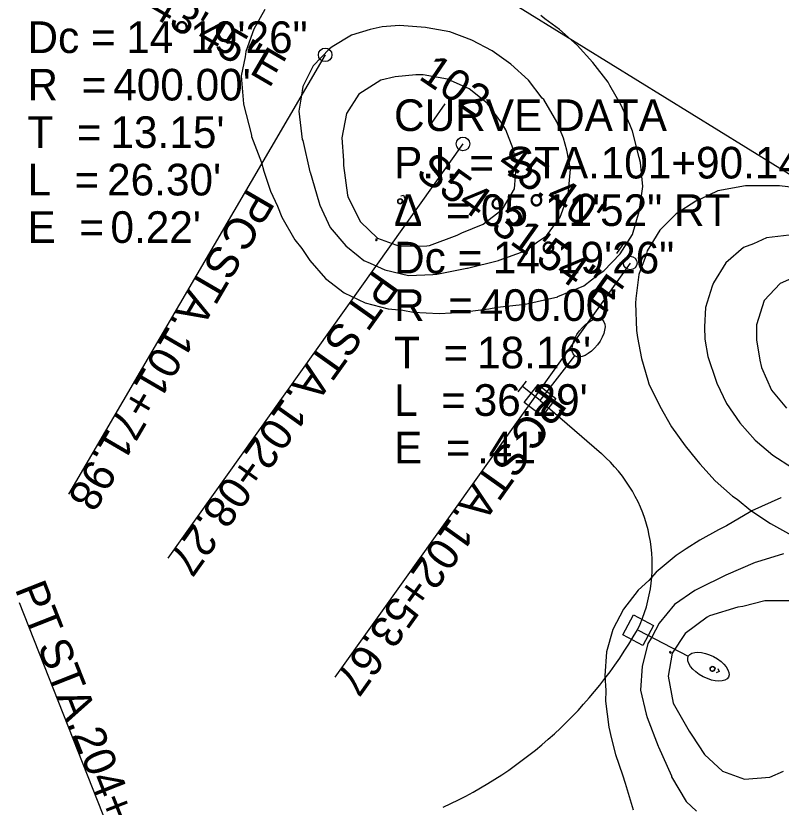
# Model space of a CAD drawing. Extents: x 1598538 to 1602183, y 285823 to 288192.
# Drawn here: x 1600781.1 to 1600950.3, y 286694.3 to 286869.3 of the extents above; entities that cross this region are included whole.
import ezdxf

# ---------------------------------------------------------------- set-up
doc = ezdxf.new("R2010")
doc.units = 0
for name, color, linetype in [('CM_Corridor_Conceptual', 7, 'Continuous'), ('CM_Corridor_Range_Conceptual', 7, 'Continuous'), ('Default', 7, 'Continuous'), ('MD_P_AGB_B', 7, 'Continuous'), ('PV_P_Curb', 7, 'Continuous'), ('PV_P_EOP', 7, 'Continuous'), ('RW_P_Esmt_LA', 7, 'Continuous'), ('RW_P_Esmt_TMP', 7, 'Continuous')]:
    doc.layers.add(name, color=color, linetype=linetype)

msp = doc.modelspace()

# ---------------------------------------------------------------- linework, layer by layer
at = {"layer": 'Default'}
for points in [[(1600836.17, 286870.71), (1600833.67, 286866.3), (1600831.92, 286861.36), (1600831.8, 286860.21), (1600830.92, 286855.99), (1600831.42, 286849.8), (1600831.42, 286849.74), (1600833.17, 286842.9), (1600833.17, 286842.61), (1600835.42, 286836.83), (1600835.92, 286834.96), (1600837.42, 286830.49), (1600838.92, 286827.18), (1600839.92, 286824.74), (1600842.8, 286819.71), (1600844.3, 286817.86), (1600846.05, 286815.18), (1600849.55, 286811.18), (1600853.67, 286808.02), (1600858.3, 286805.83), (1600863.42, 286804.52), (1600866.67, 286804.21), (1600868.92, 286803.74), (1600874.67, 286803.43), (1600877.42, 286803.61), (1600880.92, 286803.86), (1600885.67, 286804.52), (1600887.55, 286804.86), (1600893.67, 286805.55), (1600894.05, 286805.61), (1600900.92, 286807.15), (1600900.92, 286807.18), (1600906.67, 286809.58), (1600910.05, 286812.24), (1600911.05, 286812.9), (1600914.67, 286816.68), (1600917.42, 286820.96), (1600918.92, 286825.99), (1600919.05, 286826.96), (1600919.67, 286831.55), (1600919.17, 286836.83), (1600918.92, 286837.93), (1600917.42, 286843.74), (1600916.8, 286845.24), (1600914.92, 286849.55), (1600912.42, 286853.86), (1600912.05, 286854.58), (1600908.67, 286858.93), (1600905.17, 286862.8), (1600901.3, 286866.27), (1600898.05, 286868.65), (1600897.17, 286869.36)], [(1600956.05, 286830.96), (1600949.92, 286831.65), (1600949.55, 286831.68), (1600942.55, 286831.71), (1600942.42, 286831.71), (1600936.3, 286830.58), (1600932.42, 286828.77), (1600931.42, 286828.33), (1600927.05, 286825.49), (1600923.42, 286821.9), (1600920.67, 286817.33), (1600920.42, 286816.43), (1600918.8, 286812.08), (1600918.17, 286806.8), (1600918.05, 286805.71), (1600918.3, 286799.68), (1600918.55, 286798.11), (1600919.42, 286793.49), (1600920.8, 286788.74), (1600921.05, 286787.93), (1600923.42, 286782.96), (1600926.05, 286778.36), (1600929.05, 286774.15), (1600931.55, 286771.11), (1600932.3, 286770.21), (1600935.67, 286766.43), (1600939.55, 286763.08), (1600940.55, 286762.36), (1600943.55, 286759.9), (1600947.92, 286756.99), (1600952.55, 286754.46)], [(1600865.8, 286828.74), (1600865.55, 286828.55), (1600865.55, 286828.55), (1600865.8, 286828.74), (1600865.8, 286828.74)], [(1600866.17, 286829.46), (1600866.8, 286829.61), (1600867.05, 286828.9)], [(1600865.55, 286828.02), (1600865.8, 286827.8), (1600865.8, 286827.8), (1600865.55, 286828.02), (1600865.55, 286828.02)], [(1600953.3, 286820.93), (1600947.05, 286820.15), (1600944.17, 286818.86), (1600941.92, 286818.02), (1600938.05, 286814.65), (1600935.3, 286810.27), (1600935.05, 286809.46), (1600933.55, 286804.8), (1600933.3, 286800.49), (1600933.42, 286797.77), (1600934.05, 286793.96), (1600935.92, 286788.49), (1600936.05, 286788.08), (1600938.17, 286783.55), (1600941.17, 286779.24), (1600944.55, 286775.46), (1600948.42, 286772.11), (1600952.8, 286769.3)], [(1600860.8, 286819.55), (1600860.92, 286819.77), (1600860.92, 286819.77), (1600860.8, 286819.55), (1600860.8, 286819.55)], [(1600955.05, 286812.33), (1600950.05, 286810.08), (1600946.55, 286806.33), (1600944.8, 286800.93), (1600944.8, 286797.65), (1600945.55, 286793.11), (1600945.92, 286791.49), (1600948.17, 286786.49), (1600951.42, 286782.52)], [(1600950.3, 286762.71), (1600950.17, 286762.71), (1600943.8, 286759.8), (1600943.55, 286759.65), (1600938.17, 286756.52), (1600936.42, 286755.61), (1600932.3, 286753.33), (1600929.3, 286751.4), (1600927.05, 286749.93), (1600922.67, 286746.21), (1600921.05, 286744.43), (1600918.67, 286742.27), (1600915.42, 286738.08), (1600913.05, 286733.55), (1600911.67, 286728.61), (1600911.3, 286723.3), (1600911.55, 286720.08), (1600911.42, 286717.74), (1600912.17, 286711.96), (1600912.8, 286709.4), (1600913.67, 286705.9), (1600915.17, 286701.43), (1600915.8, 286699.58), (1600917.55, 286693.65)], [(1600950.8, 286750.3), (1600944.8, 286748.46), (1600944.55, 286748.4), (1600938.05, 286745.61), (1600938.05, 286745.58), (1600931.92, 286742.58), (1600931.17, 286742.18), (1600926.67, 286739.11), (1600923.3, 286734.99), (1600921.67, 286731.86), (1600920.8, 286730.49), (1600920.42, 286728.93), (1600919.55, 286725.49), (1600919.17, 286720.15), (1600920.42, 286714.86), (1600920.67, 286714.08), (1600923.05, 286707.74), (1600923.17, 286707.65), (1600926.05, 286701.18), (1600926.05, 286700.99), (1600929.3, 286695.52), (1600931.55, 286693.36)], [(1600952.17, 286739.9), (1600946.67, 286739.93), (1600941.8, 286738.65), (1600940.67, 286738.49), (1600934.42, 286736.58), (1600933.92, 286736.3), (1600929.05, 286732.71), (1600926.17, 286728.36), (1600925.3, 286723.21), (1600926.42, 286717.3), (1600926.67, 286716.74), (1600929.92, 286711.05), (1600930.55, 286710.18), (1600933.3, 286705.9), (1600937.3, 286702.21), (1600942.17, 286700.46), (1600947.8, 286700.93), (1600950.8, 286702.21)], [(1600934.8, 286725.27), (1600934.55, 286725.05), (1600934.55, 286725.05), (1600934.8, 286725.27), (1600934.8, 286725.27)], [(1600936.3, 286724.96), (1600936.55, 286724.27), (1600935.92, 286723.99)]]:
    msp.add_lwpolyline(points, dxfattribs=at)
for points in [[(1600903.17, 286829.65), (1600903.3, 286830.49), (1600903.67, 286835.36), (1600902.92, 286839.61), (1600902.17, 286842.24), (1600900.67, 286845.83), (1600897.8, 286850.77), (1600897.42, 286851.11), (1600894.42, 286855.05), (1600890.55, 286858.61), (1600886.42, 286861.55), (1600881.92, 286863.93), (1600877.05, 286865.71), (1600872.05, 286866.65), (1600871.67, 286866.74), (1600865.92, 286867.15), (1600862.05, 286866.83), (1600859.42, 286866.27), (1600855.3, 286864.99), (1600851.05, 286862.46), (1600850.42, 286862.02), (1600846.8, 286858.21), (1600844.55, 286853.65), (1600844.17, 286851.27), (1600843.67, 286848.18), (1600844.42, 286841.9), (1600844.55, 286841.68), (1600846.05, 286834.8), (1600846.17, 286834.71), (1600848.05, 286828.18), (1600848.3, 286827.4), (1600850.55, 286822.49), (1600854.05, 286818.4), (1600856.8, 286816.21), (1600858.05, 286815.18), (1600859.42, 286814.58), (1600862.67, 286813.08), (1600867.92, 286811.83), (1600873.3, 286812.08), (1600874.17, 286812.18), (1600880.8, 286813.46), (1600880.92, 286813.49), (1600887.8, 286815.18), (1600887.92, 286815.27), (1600893.92, 286817.4), (1600896.42, 286819.3), (1600898.42, 286820.61), (1600901.42, 286824.77)], [(1600891.8, 286836.65), (1600891.05, 286839.86), (1600889.42, 286844.08), (1600888.55, 286845.58), (1600885.3, 286849.96), (1600881.3, 286853.11), (1600876.55, 286855.27), (1600871.17, 286856.24), (1600869.55, 286856.27), (1600864.92, 286855.83), (1600861.8, 286855.02), (1600856.92, 286851.99), (1600854.17, 286847.71), (1600853.17, 286842.33), (1600853.55, 286837.27), (1600853.55, 286836.15), (1600854.42, 286829.65), (1600854.55, 286829.08), (1600857.3, 286823.71), (1600861.05, 286820.11), (1600865.92, 286818.36), (1600871.92, 286818.43), (1600872.55, 286818.52), (1600878.67, 286820.74), (1600879.67, 286821.3), (1600884.42, 286823.24), (1600888.67, 286826.55), (1600891.3, 286830.99)], [(1600865.55, 286828.27), (1600865.55, 286828.02), (1600865.8, 286827.8), (1600866.05, 286827.74), (1600866.3, 286827.8), (1600866.42, 286827.99), (1600866.55, 286828.24), (1600866.55, 286828.52), (1600866.3, 286828.71), (1600866.05, 286828.8), (1600865.8, 286828.74), (1600865.55, 286828.55)], [(1600865.55, 286828.27), (1600865.55, 286828.02), (1600865.8, 286827.8), (1600866.05, 286827.74), (1600866.3, 286827.8), (1600866.42, 286827.99), (1600866.55, 286828.24), (1600866.55, 286828.52), (1600866.3, 286828.71), (1600866.05, 286828.8), (1600865.8, 286828.74), (1600865.55, 286828.55)], [(1600866.05, 286828.8), (1600865.8, 286828.74), (1600865.8, 286828.74), (1600866.05, 286828.8)], [(1600866.3, 286828.71), (1600866.05, 286828.8), (1600866.05, 286828.8), (1600866.3, 286828.71)], [(1600866.55, 286828.52), (1600866.3, 286828.71), (1600866.3, 286828.71), (1600866.55, 286828.52)], [(1600865.55, 286828.55), (1600865.55, 286828.27), (1600865.55, 286828.27), (1600865.55, 286828.55)], [(1600865.55, 286828.27), (1600865.55, 286828.02), (1600865.55, 286828.02), (1600865.55, 286828.27)], [(1600865.8, 286827.8), (1600866.05, 286827.74), (1600866.05, 286827.74), (1600865.8, 286827.8)], [(1600866.05, 286827.74), (1600866.3, 286827.8), (1600866.3, 286827.8), (1600866.05, 286827.74)], [(1600866.3, 286827.8), (1600866.42, 286827.99), (1600866.42, 286827.99), (1600866.3, 286827.8)], [(1600866.42, 286827.99), (1600866.55, 286828.24), (1600866.55, 286828.24), (1600866.42, 286827.99)], [(1600866.55, 286828.24), (1600866.55, 286828.52), (1600866.55, 286828.52), (1600866.55, 286828.24)], [(1600860.67, 286819.71), (1600860.8, 286819.55), (1600860.92, 286819.77), (1600860.8, 286819.93)], [(1600860.67, 286819.71), (1600860.8, 286819.55), (1600860.92, 286819.77), (1600860.8, 286819.93)], [(1600860.8, 286819.93), (1600860.67, 286819.71), (1600860.67, 286819.71), (1600860.8, 286819.93)], [(1600860.67, 286819.71), (1600860.8, 286819.55), (1600860.8, 286819.55), (1600860.67, 286819.71)], [(1600860.92, 286819.77), (1600860.8, 286819.93), (1600860.8, 286819.93), (1600860.92, 286819.77)], [(1600925.67, 286728.68), (1600925.67, 286728.46), (1600925.92, 286728.36), (1600925.92, 286728.58)], [(1600925.67, 286728.68), (1600925.67, 286728.46), (1600925.92, 286728.36), (1600925.92, 286728.58)], [(1600925.67, 286728.68), (1600925.67, 286728.46), (1600925.67, 286728.46), (1600925.67, 286728.68)], [(1600925.92, 286728.58), (1600925.67, 286728.68), (1600925.67, 286728.68), (1600925.92, 286728.58)], [(1600925.67, 286728.46), (1600925.92, 286728.36), (1600925.92, 286728.36), (1600925.67, 286728.46)], [(1600925.92, 286728.36), (1600925.92, 286728.58), (1600925.92, 286728.58), (1600925.92, 286728.36)], [(1600935.05, 286725.36), (1600934.8, 286725.27), (1600934.55, 286725.05), (1600934.55, 286724.77), (1600934.67, 286724.52), (1600934.92, 286724.36), (1600935.17, 286724.33), (1600935.42, 286724.43), (1600935.55, 286724.65), (1600935.67, 286724.93), (1600935.55, 286725.18), (1600935.3, 286725.33)], [(1600935.05, 286725.36), (1600934.8, 286725.27), (1600934.55, 286725.05), (1600934.55, 286724.77), (1600934.67, 286724.52), (1600934.92, 286724.36), (1600935.17, 286724.33), (1600935.42, 286724.43), (1600935.55, 286724.65), (1600935.67, 286724.93), (1600935.55, 286725.18), (1600935.3, 286725.33)], [(1600934.55, 286725.05), (1600934.55, 286724.77), (1600934.55, 286724.77), (1600934.55, 286725.05)], [(1600934.55, 286724.77), (1600934.67, 286724.52), (1600934.67, 286724.52), (1600934.55, 286724.77)], [(1600934.67, 286724.52), (1600934.92, 286724.36), (1600934.92, 286724.36), (1600934.67, 286724.52)], [(1600935.05, 286725.36), (1600934.8, 286725.27), (1600934.8, 286725.27), (1600935.05, 286725.36)], [(1600934.92, 286724.36), (1600935.17, 286724.33), (1600935.17, 286724.33), (1600934.92, 286724.36)], [(1600935.3, 286725.33), (1600935.05, 286725.36), (1600935.05, 286725.36), (1600935.3, 286725.33)], [(1600935.17, 286724.33), (1600935.42, 286724.43), (1600935.42, 286724.43), (1600935.17, 286724.33)], [(1600935.55, 286725.18), (1600935.3, 286725.33), (1600935.3, 286725.33), (1600935.55, 286725.18)], [(1600935.42, 286724.43), (1600935.55, 286724.65), (1600935.55, 286724.65), (1600935.42, 286724.43)], [(1600935.67, 286724.93), (1600935.55, 286725.18), (1600935.55, 286725.18), (1600935.67, 286724.93)], [(1600935.55, 286724.65), (1600935.67, 286724.93), (1600935.67, 286724.93), (1600935.55, 286724.65)]]:
    msp.add_lwpolyline(points, close=True, dxfattribs=at)
at = {"layer": 'MD_P_AGB_B'}
for p, q in [((1600873.15, 286845.69), (1600875.97, 286849.82)), ((1600913.92, 286816.75), (1600915.67, 286819.19))]:
    msp.add_line(p, q, dxfattribs=at)
at = {"layer": 'PV_P_Curb'}
for p, q in [((1600849.47, 286860.65), (1600792.76, 286763.49)), ((1600879.94, 286840.96), (1600814.66, 286749.34)), ((1600916.91, 286814.62), (1600851.63, 286723)), ((1600823.21, 286634.77), (1600781.94, 286739.43))]:
    msp.add_line(p, q, dxfattribs=at)
for centre in [(1600849.47, 286860.65), (1600879.94, 286840.96), (1600916.91, 286814.62)]:
    msp.add_circle(centre, 1.5, dxfattribs=at)
at = {"layer": 'RW_P_Esmt_LA'}
for p, q in [((1600896.99, 286784.22), (1600904.63, 286794.11)), ((1600918.66, 286733.42), (1600929.75, 286727.65))]:
    msp.add_line(p, q, dxfattribs=at)
for points in [[(1600893.48, 286783.77), (1600896.54, 286787.73), (1600900.5, 286784.67), (1600897.44, 286780.72)], [(1600917.6, 286736.79), (1600922.03, 286734.48), (1600919.73, 286730.05), (1600915.29, 286732.35)]]:
    msp.add_lwpolyline(points, close=True, dxfattribs=at)
for centre, major_axis in [((1600907.69, 286798.07), (3.06, 3.96)), ((1600934.19, 286725.34), (4.44, -2.31))]:
    msp.add_ellipse(centre, major_axis=major_axis, ratio=0.5, dxfattribs=at)
at = {"layer": 'RW_P_Esmt_TMP'}
for p, q in [((1601041.07, 286779.12), (1600856.86, 286893.09)), ((1600892.13, 286786.11), (1600893.96, 286788.49)), ((1600896.98, 286784.21), (1600893.06, 286787.32)), ((1600896.98, 286784.21), (1600910.53, 286772.46))]:
    msp.add_line(p, q, dxfattribs=at)
for centre, radius, start, end in [((1600889.15, 286747.79), 32.64, 334.0626, 49.0812), ((1600836.35, 286780.28), 94.53, 294.5176, 330.3499)]:
    msp.add_arc(centre, radius, start, end, dxfattribs=at)

# ---------------------------------------------------------------- texts
at = {"layer": 'CM_Corridor_Conceptual'}
for s, p in [('Dc = ', (1600783.66, 286861.06)), ('14°19\'26"', (1600805.51, 286861.06)), ('R  = ', (1600783.66, 286850.56)), ("400.00'", (1600802.62, 286850.56)), ('CURVE DATA', (1600864.7, 286843.81)), ('T  = ', (1600783.66, 286840.06)), ("13.15'", (1600802.01, 286840.06)), ('P.I. = STA. ', (1600864.7, 286833.31)), ('101+90.14', (1600910.37, 286833.31)), ('L  = ', (1600783.66, 286829.56)), ("26.30'", (1600801.26, 286829.56)), ('Δ  = ', (1600864.7, 286822.81)), ('05°11\'52" RT', (1600883.89, 286822.81)), ('E  = ', (1600783.66, 286819.06)), ("0.22'", (1600802.01, 286819.06)), ('Dc = ', (1600864.7, 286812.31)), ('14°19\'26"', (1600886.55, 286812.31)), ('R  = ', (1600864.7, 286801.81)), ("400.00'", (1600883.66, 286801.81)), ('T  = ', (1600864.7, 286791.31)), ("18.16'", (1600883.05, 286791.31)), ('L  = ', (1600864.7, 286780.81)), ("36.29'", (1600882.3, 286780.81)), ('E  = ', (1600864.7, 286770.31)), (".41'", (1600883.05, 286770.31))]:
    msp.add_text(s, height=7, dxfattribs=at).set_placement(p)
at = {"layer": 'CM_Corridor_Range_Conceptual'}
msp.add_text("45.40'", height=7, rotation=324.5316, dxfattribs=at).set_placement((1600887.16, 286835.95))
at = {"layer": 'MD_P_AGB_B'}
msp.add_text('102', height=7, rotation=325.7158, dxfattribs=at).set_placement((1600869.9, 286855.47))
at = {"layer": 'PV_P_Curb'}
for s, rotation, p in [('PC', 239.7293, (1600832.52, 286831.4)), (' STA. ', 239.7293, (1600826.74, 286821.5)), ('PT', 234.5316, (1600860.4, 286813.37)), (' STA. ', 234.5316, (1600854, 286804.38)), ('101+71.98', 239.7293, (1600814.83, 286801.1)), ('PC', 234.5316, (1600897.5, 286787.2)), ('102+08.27', 234.5316, (1600840.29, 286785.13)), (' STA. ', 234.5316, (1600890.85, 286777.86)), ('102+53.67', 234.5316, (1600877.14, 286758.62)), ('PT', 291.5214, (1600780.81, 286742.58)), (' STA. ', 291.5214, (1600784.86, 286732.31)), ('204+22.02', 291.5214, (1600793.53, 286710.33))]:
    msp.add_text(s, height=7, rotation=rotation, dxfattribs=at).set_placement(p)
at = {"layer": 'PV_P_EOP'}
for s, rotation, p in [('S59°43\'45"E', 329.7293, (1600792.46, 286880.03)), ('S54°31\'54"E', 324.5316, (1600869.19, 286833.89))]:
    msp.add_text(s, height=7, rotation=rotation, dxfattribs=at).set_placement(p)

doc.saveas('drawing.dxf')
